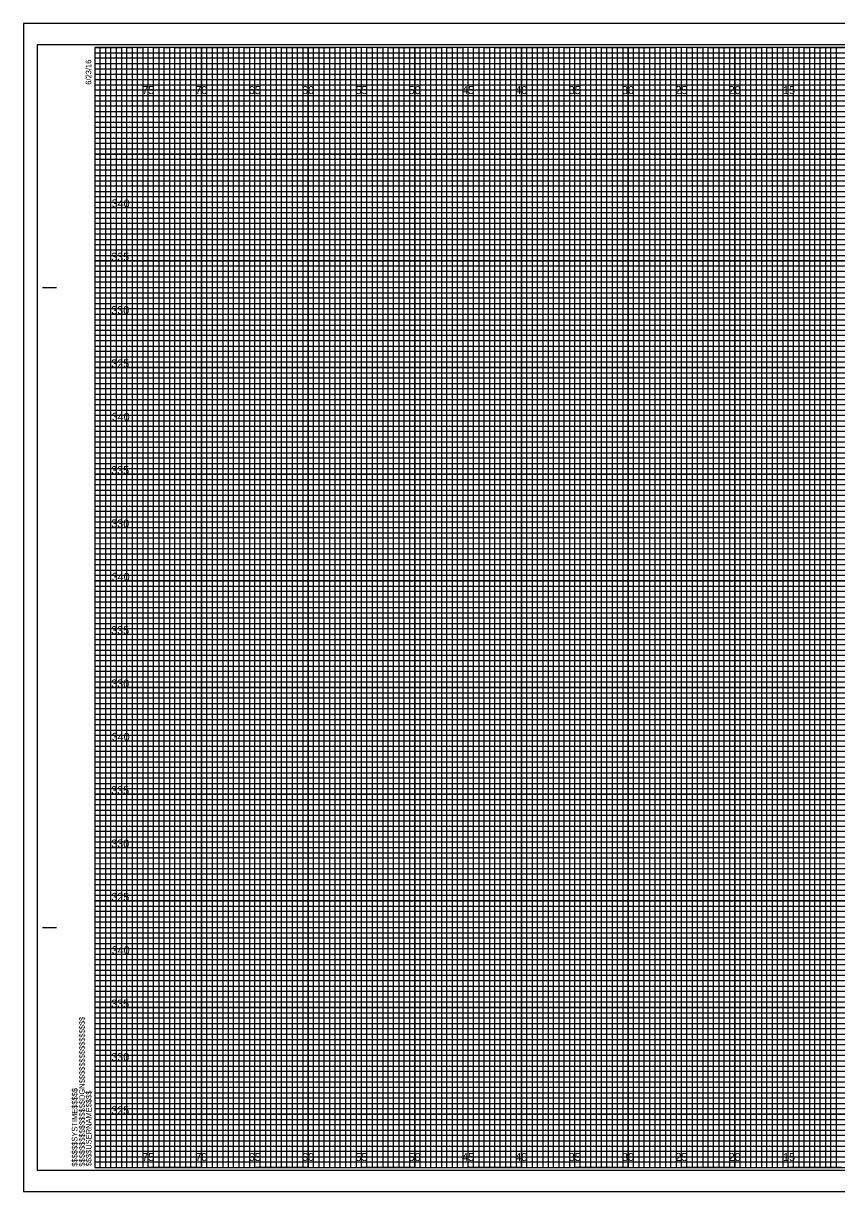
# Model space of a CAD drawing. Extents: x -7 to 162, y -2 to 107.
# Drawn here: x -6.7 to 69.5, y -2.3 to 107.3 of the extents above; entities that cross this region are included whole.
import ezdxf

# ---------------------------------------------------------------- set-up
doc = ezdxf.new("R2010")
doc.units = 0
for name, color, linetype in [('Prop XS Elevation Labels', 7, 'Continuous'), ('Prop XS Offset Labels', 7, 'Continuous'), ('Sheet Cross Section CELL', 7, 'Continuous'), ('Sheet Cross Section Grid Major CELL', 7, 'Continuous'), ('Sheet Cross Section Grid Middle CELL', 7, 'Continuous'), ('Sheet Cross Section Grid Minor 1 CELL', 7, 'Continuous'), ('Sheet Cross Section Grid Minor 2 CELL', 7, 'Continuous'), ('Sheet Cutting Line CELL', 7, 'Continuous'), ('Sheet DOT Grid CELL', 7, 'Continuous'), ('Sheet Plot Border Inside CELL', 7, 'Continuous'), ('Sheet Plot Border Outside CELL', 7, 'Continuous')]:
    doc.layers.add(name, color=color, linetype=linetype)

msp = doc.modelspace()

# ---------------------------------------------------------------- linework, layer by layer
at = {"layer": 'Sheet Cross Section CELL'}
for p, q in [((-4.9, 82.5), (-3.65, 82.5)), ((-4.85, 82.5), (-3.6, 82.5)), ((-4.9, 22.5), (-3.65, 22.5)), ((-4.85, 22.5), (-3.6, 22.5)), ((0, 0), (0, 0)), ((0, 0), (0, 0)), ((0, 0), (0, 0)), ((0, 0), (0, 0)), ((0, 0), (0, 0)), ((0, 0), (0, 0)), ((0, 0), (0, 0))]:
    msp.add_line(p, q, dxfattribs=at)
msp.add_lwpolyline([(160, 105), (0, 105), (0, 0), (160, 0)], close=True, dxfattribs=at)
at = {"layer": 'Sheet Cross Section Grid Major CELL'}
for p, q in [((5, 105), (0, 105)), ((5, 0), (5, 105)), ((15, 105), (10, 105)), ((10, 105), (10, 0)), ((15, 0), (15, 105)), ((25, 105), (20, 105)), ((20, 105), (20, 0)), ((25, 0), (25, 105)), ((35, 105), (30, 105)), ((30, 105), (30, 0)), ((35, 0), (35, 105)), ((45, 105), (40, 105)), ((40, 105), (40, 0)), ((45, 0), (45, 105)), ((55, 105), (50, 105)), ((50, 105), (50, 0)), ((55, 0), (55, 105)), ((65, 105), (60, 105)), ((60, 105), (60, 0)), ((65, 0), (65, 105)), ((10, 0), (5, 0)), ((20, 0), (15, 0)), ((30, 0), (25, 0)), ((40, 0), (35, 0)), ((50, 0), (45, 0)), ((60, 0), (55, 0)), ((70, 0), (65, 0))]:
    msp.add_line(p, q, dxfattribs=at)
for points in [[(0, 100), (160, 100), (160, 95), (0, 95)], [(0, 90), (160, 90), (160, 85), (0, 85)], [(0, 80), (160, 80), (160, 75), (0, 75)], [(0, 70), (160, 70), (160, 65), (0, 65)], [(0, 60), (160, 60), (160, 55), (0, 55)], [(0, 50), (160, 50), (160, 45), (0, 45)], [(0, 40), (160, 40), (160, 35), (0, 35)], [(0, 30), (160, 30), (160, 25), (0, 25)], [(0, 20), (160, 20), (160, 15), (0, 15)], [(0, 10), (160, 10), (160, 5), (0, 5)]]:
    msp.add_lwpolyline(points, dxfattribs=at)
at = {"layer": 'Sheet Cross Section Grid Middle CELL'}
for points in [[(0, 105), (2.5, 105), (2.5, 0), (7.5, 0), (7.5, 105), (12.5, 105), (12.5, 0), (17.5, 0), (17.5, 105), (22.5, 105), (22.5, 0), (27.5, 0), (27.5, 105), (32.5, 105), (32.5, 0), (37.5, 0), (37.5, 105), (42.5, 105), (42.5, 0), (47.5, 0), (47.5, 105), (52.5, 105), (52.5, 0), (57.5, 0), (57.5, 105), (62.5, 105), (62.5, 0), (67.5, 0), (67.5, 105), (72.5, 105)], [(0, 102.5), (137.5, 102.5)], [(0, 92.5), (160, 92.5), (160, 97.5), (0, 97.5)], [(0, 82.5), (160, 82.5), (160, 87.5), (0, 87.5)], [(0, 72.5), (160, 72.5), (160, 77.5), (0, 77.5)], [(0, 62.5), (160, 62.5), (160, 67.5), (0, 67.5)], [(0, 52.5), (160, 52.5), (160, 57.5), (0, 57.5)], [(0, 42.5), (160, 42.5), (160, 47.5), (0, 47.5)], [(0, 32.5), (160, 32.5), (160, 37.5), (0, 37.5)], [(0, 22.5), (160, 22.5), (160, 27.5), (0, 27.5)], [(0, 12.5), (160, 12.5), (160, 17.5), (0, 17.5)], [(0, 2.5), (160, 2.5), (160, 7.5), (0, 7.5)]]:
    msp.add_lwpolyline(points, dxfattribs=at)
at = {"layer": 'Sheet Cross Section Grid Minor 1 CELL'}
for p, q in [((0, 104.5), (130, 104.5)), ((130, 103.99), (0, 103.99)), ((0, 103.99), (0, 103.5)), ((0, 103.5), (130, 103.5)), ((130, 102.95), (0, 102.95)), ((0, 102.95), (0, 102)), ((0, 102), (160, 102))]:
    msp.add_line(p, q, dxfattribs=at)
for points in [[(0, 101.5), (135, 101.5), (160, 101.5), (160, 101), (0, 101)], [(0, 100.5), (160, 100.5), (160, 99.5), (0, 99.5)], [(0, 99), (160, 99), (160, 98.5), (0, 98.49)], [(0, 98), (160, 98), (160, 97), (0, 97)], [(0, 96.5), (160, 96.5), (160, 96), (0, 96)], [(0, 95.5), (160, 95.5), (160, 94.5), (0, 94.5)], [(0, 94), (160, 94), (160, 93.5), (0, 93.5)], [(0, 93), (160, 93), (160, 92), (0, 92)], [(0, 91.5), (160, 91.5), (160, 91), (0, 91)], [(0, 90.5), (160, 90.5), (160, 89.5), (0, 89.5)], [(0, 89), (160, 89), (160, 88.5), (0, 88.5)], [(0, 88), (160, 88), (160, 86.98), (160, 86.5), (160, 86), (0, 86)], [(0, 87), (160, 87), (160, 86.5), (0, 86.5)], [(0, 85.5), (160, 85.5), (160, 84.5), (0, 84.52)], [(0, 84.52), (160, 84.5), (160, 84), (0, 84)], [(0, 83.5), (160, 83.5), (160, 83), (0, 83)], [(0, 82), (160, 82), (160, 81.5), (0, 81.5)], [(0, 81), (160, 81), (160, 80.5), (0, 80.5)], [(-0.04, 79.45), (160, 79.45), (160, 78.94), (-0.04, 78.94)], [(0, 78.5), (160, 78.5), (160, 78), (0, 78)], [(0, 77), (160, 77), (160, 76.5), (0, 76.5)], [(0, 76), (160, 76), (160, 75.5), (0, 75.5)], [(0, 74.5), (160, 74.5), (160, 74), (0, 74)], [(0, 73.5), (160, 73.5), (160, 73), (0, 73)], [(0, 72), (160, 72), (160, 71.5), (0, 71.5)], [(0, 71), (160, 71), (160, 70.5), (0, 70.5)], [(0, 69.5), (160, 69.5), (160, 68.99), (0, 69)], [(0, 68.5), (160, 68.5), (160, 68), (0, 68)], [(0, 67), (160, 67), (160, 66.5), (0, 66.5)], [(0, 66), (160, 66), (160, 65.5), (0, 65.5)], [(0, 64.5), (160, 64.5), (160, 64), (0, 64)], [(0, 63.5), (160, 63.5), (160, 63), (0, 63)], [(0, 62), (160, 62), (160, 61.5), (0, 61.5)], [(0, 61), (160, 61), (160, 60.5), (0, 60.5)], [(0, 59.5), (160, 59.5), (160, 59), (0, 59)], [(0, 58.5), (160.03, 58.45), (160, 58), (0, 58)], [(0, 57), (160, 57), (160, 56.5), (0, 56.5)], [(0, 56), (160, 56), (160, 55.5), (0, 55.5)], [(0, 54.5), (160, 54.5), (160, 54), (0, 54)], [(0, 53.5), (160, 53.5), (160, 53), (0, 53)], [(0, 52), (160, 52), (160, 51.5), (0, 51.5)], [(0, 51), (160, 51), (160, 50.5), (0, 50.5)], [(0, 49.5), (160, 49.5), (160, 49), (0, 49)], [(0, 48.5), (160, 48.5), (160, 48), (0, 48)], [(0, 47), (160, 47), (160, 46.5), (0, 46.5)], [(0, 46), (160, 46), (160, 45.5), (0, 45.5)], [(0, 44.5), (160, 44.5), (160, 44), (0, 44)], [(0, 43.5), (160, 43.5), (160, 43), (0, 43)], [(0, 42), (160, 42), (160, 41.5), (0, 41.5)], [(0, 41), (160, 41), (160, 40.5), (0, 40.5)], [(0, 39.5), (160, 39.5), (160, 38.99), (0, 39)], [(0, 38.5), (160, 38.5), (160, 38), (0, 38)], [(0, 37), (160, 37), (160, 36.5), (0, 36.5)], [(0, 36), (160, 36), (160, 35.5), (0, 35.5)], [(0, 34.5), (160, 34.5), (160, 34), (0, 34)], [(0, 33.5), (160, 33.5), (160, 33), (0, 33)], [(0, 32), (160, 32), (160, 31.5), (0, 31.5)], [(0, 31), (160, 31), (160, 30.5), (0, 30.5)], [(0, 29.5), (160, 29.5), (160, 29), (0, 29)], [(0, 28.5), (160.03, 28.46), (160, 28), (0, 28)], [(0, 27), (160, 27), (160, 26.5), (0, 26.5)], [(0, 26), (160, 26), (160, 25.5), (0, 25.5)], [(0, 24.5), (160, 24.5), (160, 24), (0, 24)], [(0, 23.5), (160, 23.5), (160, 23), (0, 23)], [(0, 22), (160, 22), (160, 21.5), (0, 21.5)], [(0, 21), (160, 21), (160, 20.5), (0, 20.5)], [(0, 19.5), (160, 19.5), (160, 19), (0, 19)], [(0, 18.5), (160, 18.5), (160, 18), (0, 18)], [(0, 17), (160, 17), (160, 16.5), (0, 16.5)], [(0, 16), (160, 16), (160, 15.5), (0, 15.5)], [(0, 14.5), (160, 14.5), (160, 14), (0, 14)], [(0, 13.5), (160, 13.5), (160, 13), (0, 13)], [(0, 12), (160, 12), (160, 11.5), (0, 11.5)], [(0, 11), (160, 11), (160, 10.5), (0, 10.5)], [(0, 9.5), (160, 9.5), (160, 9), (0, 9)], [(0, 8.5), (160, 8.5), (160, 8), (0, 8)], [(0, 7), (160, 7), (160, 6.5), (0, 6.5)], [(0, 6), (160, 6), (160, 5.5), (0, 5.5)], [(0, 4.5), (160, 4.5), (160, 4), (0, 4)], [(0, 3.5), (160, 3.5), (160, 3), (0, 3)], [(0, 2), (160, 2), (160, 1.5), (0, 1.5)], [(0, 1), (160, 1), (160, 0.5), (0, 0.5)]]:
    msp.add_lwpolyline(points, dxfattribs=at)
at = {"layer": 'Sheet Cross Section Grid Minor 2 CELL'}
for points in [[(0, 0), (0.5, 0), (0.5, 105), (1, 105), (1, 0)], [(1, 0), (1.5, 0), (1.5, 105), (2, 105), (2, 0)], [(2.5, 0), (3, 0), (3, 105), (3.5, 105), (3.5, 0)], [(3.5, 0), (4, 0), (4, 105), (4.5, 105), (4.5, 0)], [(5, 0), (5.5, 0), (5.5, 105), (6, 105), (6, 0)], [(6, 0), (6.5, 0), (6.5, 105), (7, 105), (7, 0)], [(7.5, 0), (8, 0), (8, 105), (8.5, 105), (8.5, 0)], [(8.5, 0), (9, 0), (9, 105), (9.5, 105), (9.5, 0)], [(10, 0), (10.5, 0), (10.5, 105), (11, 105), (11, 0)], [(11, 0), (11.5, 0), (11.5, 105), (12, 105), (12, 0)], [(12.5, 0), (13, 0), (13, 105), (13.5, 105), (13.5, 0)], [(13.5, 0), (14, 0), (14, 105), (14.5, 105), (14.5, 0)], [(15, 0), (15.5, 0), (15.5, 105), (16, 105), (16, 0)], [(16, 0), (16.5, 0), (16.5, 105), (17, 105), (17, 0)], [(17.5, 0), (18, 0), (18, 105), (18.5, 105), (18.5, 0)], [(18.5, 0), (19, 0), (19, 105), (19.5, 105), (19.5, 0)], [(20, 0), (20.5, 0), (20.5, 105), (21, 105), (21, 0)], [(21, 0), (21.5, 0), (21.5, 105), (22, 105), (22, 0)], [(22.5, 0), (23, 0), (23, 105), (23.5, 105), (23.5, 0)], [(23.5, 0), (24, 0), (24, 105), (24.5, 105), (24.5, 0)], [(25, 0), (25.5, 0), (25.5, 105), (26, 105), (26, 0)], [(26, 0), (26.5, 0), (26.5, 105), (27, 105), (27, 0)], [(27.5, 0), (28, 0), (28, 105), (28.5, 105), (28.5, 0)], [(28.5, 0), (29, 0), (29, 105), (29.5, 105), (29.5, 0)], [(30, 0), (30.5, 0), (30.5, 105), (31, 105), (31, 0)], [(31, 0), (31.5, 0), (31.5, 105), (32, 105), (32, 0)], [(32.5, 0), (33, 0), (33, 105), (33.5, 105), (33.5, 0)], [(33.5, 0), (34, 0), (34, 105), (34.5, 105), (34.5, 0)], [(35, 0), (35.5, 0), (35.5, 105), (36, 105), (36, 0)], [(36, 0), (36.5, 0), (36.5, 105), (37, 105), (37, 0)], [(37.5, 0), (38, 0), (38, 105), (38.5, 105), (38.5, 0)], [(38.5, 0), (39, 0), (39, 105), (39.5, 105), (39.5, 0)], [(40, 0), (40.5, 0), (40.5, 105), (41, 105), (41, 0)], [(41, 0), (41.5, 0), (41.5, 105), (42, 105), (42, 0)], [(42.5, 0), (43, 0), (43, 105), (43.5, 105), (43.5, 0)], [(43.5, 0), (44, 0), (44, 105), (44.5, 105), (44.5, 0)], [(45, 0), (45.5, 0), (45.5, 105), (46, 105), (46, 0)], [(46, 0), (46.5, 0), (46.5, 105), (47, 105), (47, 0)], [(47.5, 0), (48, 0), (48, 105), (48.5, 105), (48.5, 0)], [(48.5, 0), (49, 0), (49, 105), (49.5, 105), (49.5, 0)], [(50, 0), (50.5, 0), (50.5, 105), (51, 105), (51, 0)], [(51, 0), (51.5, 0), (51.5, 105), (52, 105), (52, 0)], [(52.5, 0), (53, 0), (53, 105), (53.5, 105), (53.5, 0)], [(53.5, 0), (54, 0), (54, 105), (54.5, 105), (54.5, 0)], [(55, 0), (55.5, 0), (55.5, 105), (56, 105), (56, 0)], [(56, 0), (56.5, 0), (56.5, 105), (57, 105), (57, 0)], [(57.5, 0), (58, 0), (58, 105), (58.5, 105), (58.5, 0)], [(58.5, 0), (59, 0), (59, 105), (59.5, 105), (59.5, 0)], [(60, 0), (60.5, 0), (60.5, 105), (61, 105), (61, 0)], [(61, 0), (61.5, 0), (61.5, 105), (62, 105), (62, 0)], [(62.5, 0), (63, 0), (63, 105), (63.5, 105), (63.5, 0)], [(63.5, 0), (64, 0), (64, 105), (64.5, 105), (64.5, 0)], [(65, 0), (65.5, 0), (65.5, 105), (66, 105), (66, 0)], [(66, 0), (66.5, 0), (66.5, 105), (67, 105), (67, 0)], [(67.5, 0), (68, 0), (68, 105), (68.5, 105), (68.5, 0)], [(68.5, 0), (69, 0), (69, 105), (69.5, 105), (69.5, 0)]]:
    msp.add_lwpolyline(points, dxfattribs=at)
at = {"layer": 'Sheet Cutting Line CELL'}
for p, q in [((161.65, 107.25), (-6.7, 107.25)), ((-6.7, 107.25), (-6.7, -2.25)), ((-6.7, -2.25), (161.65, -2.25))]:
    msp.add_line(p, q, dxfattribs=at)
at = {"layer": 'Sheet DOT Grid CELL'}
for p, q in [((5, 0), (5, 105)), ((10, 0), (10, 105)), ((15, 0), (15, 105)), ((20, 0), (20, 105)), ((25, 0), (25, 105)), ((30, 0), (30, 105)), ((35, 0), (35, 105)), ((40, 0), (40, 105)), ((45, 0), (45, 105)), ((50, 0), (50, 105)), ((55, 0), (55, 105)), ((60, 0), (60, 105)), ((65, 0), (65, 105)), ((0, 100), (160, 100)), ((0, 95), (160, 95)), ((0, 90), (160, 90)), ((0, 85), (160, 85)), ((0, 80), (160, 80)), ((0, 75), (160, 75)), ((0, 70), (160, 70)), ((0, 65), (160, 65)), ((0, 60), (160, 60)), ((0, 55), (160, 55)), ((0, 50), (160, 50)), ((0, 45), (160, 45)), ((0, 40), (160, 40)), ((0, 35), (160, 35)), ((0, 30), (160, 30)), ((0, 25), (160, 25)), ((0, 20), (160, 20)), ((0, 15), (160, 15)), ((0, 10), (160, 10)), ((0, 5), (160, 5))]:
    msp.add_line(p, q, dxfattribs=at)
at = {"layer": 'Sheet Plot Border Inside CELL'}
msp.add_lwpolyline([(-5.4, -0.25), (161.2, -0.25), (161.2, 105.25), (-5.4, 105.25)], close=True, dxfattribs=at)
at = {"layer": 'Sheet Plot Border Outside CELL'}
msp.add_lwpolyline([(-6.7, -2.25), (161.65, -2.25), (161.65, 107.25), (-6.7, 107.25)], close=True, dxfattribs=at)

# ---------------------------------------------------------------- texts
at = {"layer": 'Prop XS Elevation Labels'}
for s, p in [('340', (1.59, 90)), ('335', (1.54, 85)), ('330', (1.55, 80)), ('325', (1.55, 75)), ('340', (1.59, 70)), ('335', (1.54, 65)), ('330', (1.55, 60)), ('340', (1.59, 55)), ('335', (1.54, 50)), ('330', (1.55, 45)), ('340', (1.59, 40)), ('335', (1.54, 35)), ('330', (1.55, 30)), ('325', (1.55, 25)), ('340', (1.59, 20)), ('335', (1.54, 15)), ('330', (1.55, 10)), ('325', (1.55, 5))]:
    msp.add_text(s, height=0.75, dxfattribs=at).set_placement(p)
at = {"layer": 'Prop XS Offset Labels'}
for s, p in [('75', (4.44, 100.62)), ('70', (9.43, 100.62)), ('65', (14.44, 100.62)), ('60', (19.43, 100.62)), ('55', (24.44, 100.62)), ('50', (29.43, 100.62)), ('45', (34.44, 100.62)), ('40', (39.43, 100.62)), ('35', (44.44, 100.62)), ('30', (49.43, 100.62)), ('25', (54.44, 100.62)), ('20', (59.43, 100.62)), ('15', (64.53, 100.62)), ('75', (4.44, 0.62)), ('70', (9.43, 0.62)), ('65', (14.44, 0.62)), ('60', (19.43, 0.62)), ('55', (24.44, 0.62)), ('50', (29.43, 0.62)), ('45', (34.44, 0.62)), ('40', (39.43, 0.62)), ('35', (44.44, 0.62)), ('30', (49.43, 0.62)), ('25', (54.44, 0.62)), ('20', (59.43, 0.62)), ('15', (64.53, 0.62))]:
    msp.add_text(s, height=0.75, dxfattribs=at).set_placement(p)
at = {"layer": 'Sheet Cross Section CELL'}
for s, p in [('6/23/16', (-0.33, 101.5)), ('$$$$$$$$$$$$$$$$DGN$$$$$$$$$$$$$$$$', (-0.94, 0.09)), ('$$$$$$SYSTIME$$$$$', (-1.63, 0.09)), ('$$$$USERNAME$$$$', (-0.31, 0.12))]:
    msp.add_text(s, height=0.525, rotation=90, dxfattribs=at).set_placement(p)

doc.saveas('drawing.dxf')
